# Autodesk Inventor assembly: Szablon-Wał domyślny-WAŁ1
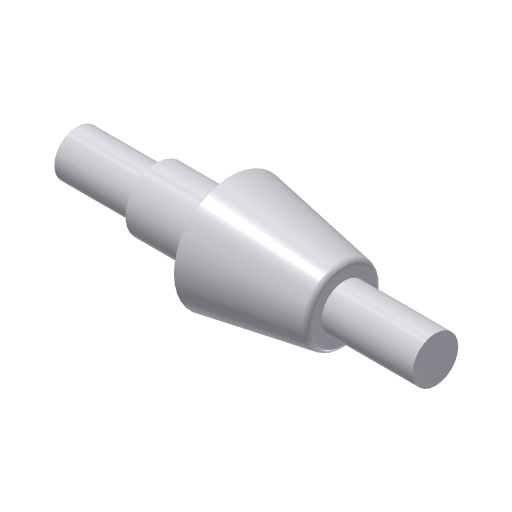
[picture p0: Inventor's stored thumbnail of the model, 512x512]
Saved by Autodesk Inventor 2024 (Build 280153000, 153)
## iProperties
ClientObjectVersion: 1
Company: ATC
Created: 2023-03
Part Number: Szablon-Wał domyślny-WAŁ1
Document SubType Name: Assembly
Designer: Andrzej Jaskulski
Checked By: A.J.
Engr Approved By: Andrzej Jaskulski
Mfg Approved By: Andrzej Jaskulski
Authority: A.J.
Author: Andrzej Jaskulski
Title: A.J.: Kurs R2024-MEP
Revision Number: 1/24
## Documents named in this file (2)
- C:\Users\AndJas\Documents\R2024-MEP\Obszar roboczy\PZ\Szablon-Wał domyślny\ContentCenter\Szablon-Wał domyślny-WAŁ1.iam
- C:\Users\AndJas\Documents\R2024-MEP\Obszar roboczy\PZ\Szablon-Wał domyślny\ContentCenter\Szablon-Wał domyślny-WAŁ1.ipt
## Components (1 placed, 1 different names)
1. Wał:1
